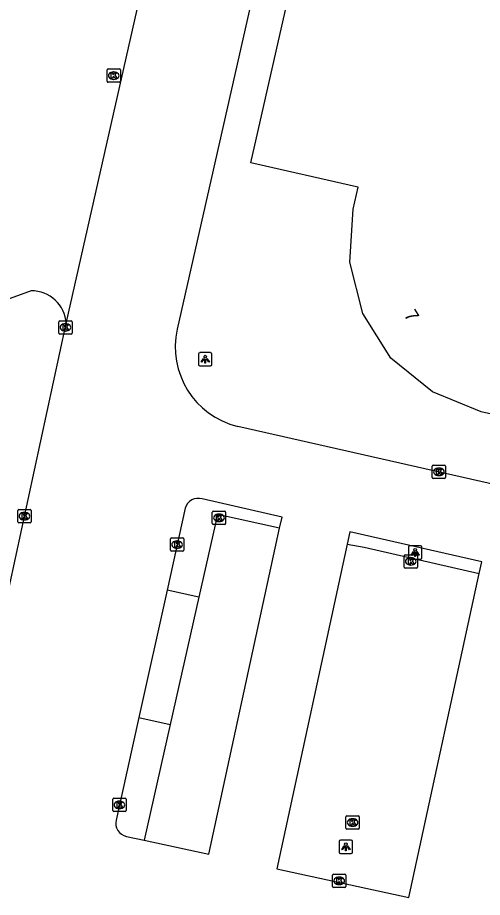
# Model space of a CAD drawing. Extents: x 162172 to 163187, y 382874 to 383684.
# Drawn here: x 162441.7 to 162476.6, y 383058.6 to 383124.7 of the extents above; entities that cross this region are included whole.
import ezdxf

# ---------------------------------------------------------------- set-up
doc = ezdxf.new("R2010")
doc.units = 0
for name, color, linetype in [('IMGEO_Kolk', 7, 'Continuous'), ('IMGEO_Lichtpunt', 7, 'Continuous'), ('IMGEO_Pand', 7, 'Continuous'), ('IMGEO_Pand_nummerreeks', 7, 'Continuous'), ('IMGEO_Parkeervlak_open', 7, 'Continuous'), ('IMGEO_Rijbaan_lokaal_open', 7, 'Continuous'), ('IMGEO_Verkeerseiland_open', 7, 'Continuous')]:
    doc.layers.add(name, color=color, linetype=linetype)

msp = doc.modelspace()

# ---------------------------------------------------------------- linework, layer by layer
at = {"layer": 'IMGEO_Kolk'}
for p, q in [((162448.37, 383119.928), (162448.37, 383120.78)), ((162448.445, 383120.854), (162449.297, 383120.854)), ((162448.858, 383120.634), (162448.883, 383120.634)), ((162449.371, 383120.78), (162449.371, 383119.928)), ((162448.881, 383120.074), (162448.856, 383120.074)), ((162449.297, 383119.854), (162448.445, 383119.854)), ((162444.742, 383101.004), (162444.742, 383101.856)), ((162444.817, 383101.93), (162445.669, 383101.93)), ((162445.23, 383101.71), (162445.255, 383101.71)), ((162445.743, 383101.856), (162445.743, 383101.004)), ((162445.669, 383100.93), (162444.817, 383100.93)), ((162445.253, 383101.15), (162445.228, 383101.15)), ((162472.796, 383090.145), (162472.796, 383090.997)), ((162472.871, 383091.071), (162473.723, 383091.071)), ((162473.284, 383090.851), (162473.309, 383090.851)), ((162473.797, 383090.997), (162473.797, 383090.145)), ((162473.307, 383090.291), (162473.282, 383090.291)), ((162473.723, 383090.071), (162472.871, 383090.071)), ((162441.663, 383086.813), (162441.663, 383087.665)), ((162441.738, 383087.739), (162442.59, 383087.739)), ((162442.151, 383087.519), (162442.176, 383087.519)), ((162442.664, 383087.665), (162442.664, 383086.813)), ((162456.278, 383086.688), (162456.278, 383087.54)), ((162456.353, 383087.614), (162457.205, 383087.614)), ((162457.279, 383087.54), (162457.279, 383086.688)), ((162442.174, 383086.959), (162442.149, 383086.959)), ((162456.766, 383087.394), (162456.791, 383087.394)), ((162442.59, 383086.739), (162441.738, 383086.739)), ((162457.205, 383086.614), (162456.353, 383086.614)), ((162456.789, 383086.834), (162456.764, 383086.834)), ((162453.209, 383085.599), (162454.061, 383085.599)), ((162453.134, 383084.673), (162453.134, 383085.525)), ((162453.622, 383085.379), (162453.647, 383085.379)), ((162454.135, 383085.525), (162454.135, 383084.673)), ((162454.061, 383084.599), (162453.209, 383084.599)), ((162453.645, 383084.819), (162453.62, 383084.819)), ((162470.685, 383083.413), (162470.685, 383084.265)), ((162470.76, 383084.339), (162471.612, 383084.339)), ((162471.686, 383084.265), (162471.686, 383083.413)), ((162471.196, 383083.559), (162471.171, 383083.559)), ((162471.173, 383084.119), (162471.198, 383084.119)), ((162471.612, 383083.339), (162470.76, 383083.339)), ((162448.798, 383065.105), (162448.798, 383065.957)), ((162448.873, 383066.031), (162449.725, 383066.031)), ((162449.286, 383065.811), (162449.311, 383065.811)), ((162449.799, 383065.957), (162449.799, 383065.105)), ((162449.725, 383065.031), (162448.873, 383065.031)), ((162449.309, 383065.251), (162449.284, 383065.251)), ((162466.317, 383063.782), (162466.317, 383064.634)), ((162466.392, 383064.708), (162467.244, 383064.708)), ((162466.805, 383064.488), (162466.83, 383064.488)), ((162467.318, 383064.634), (162467.318, 383063.782)), ((162467.244, 383063.708), (162466.392, 383063.708)), ((162466.828, 383063.928), (162466.803, 383063.928)), ((162465.307, 383059.396), (162465.307, 383060.248)), ((162465.382, 383060.322), (162466.234, 383060.322)), ((162465.795, 383060.102), (162465.82, 383060.102)), ((162466.308, 383060.248), (162466.308, 383059.396)), ((162466.234, 383059.322), (162465.382, 383059.322)), ((162465.818, 383059.542), (162465.793, 383059.542))]:
    msp.add_line(p, q, dxfattribs=at)
for points in [[(162448.37, 383119.928), (162448.37, 383120.78)], [(162448.445, 383120.854), (162449.297, 383120.854)], [(162449.371, 383120.78), (162449.371, 383119.928)], [(162448.691, 383120.554), (162448.814, 383120.554), (162448.814, 383120.403), (162448.944, 383120.554), (162449.108, 383120.554), (162448.962, 383120.403), (162449.115, 383120.154), (162448.963, 383120.154), (162448.878, 383120.318), (162448.814, 383120.251), (162448.814, 383120.154), (162448.691, 383120.154), (162448.691, 383120.554)], [(162449.297, 383119.854), (162448.445, 383119.854)], [(162444.742, 383101.004), (162444.742, 383101.856)], [(162444.817, 383101.93), (162445.669, 383101.93)], [(162445.063, 383101.63), (162445.186, 383101.63), (162445.186, 383101.479), (162445.316, 383101.63), (162445.48, 383101.63), (162445.334, 383101.479), (162445.487, 383101.23), (162445.335, 383101.23), (162445.25, 383101.394), (162445.186, 383101.327), (162445.186, 383101.23), (162445.063, 383101.23), (162445.063, 383101.63)], [(162445.743, 383101.856), (162445.743, 383101.004)], [(162445.669, 383100.93), (162444.817, 383100.93)], [(162472.796, 383090.145), (162472.796, 383090.997)], [(162472.871, 383091.071), (162473.723, 383091.071)], [(162473.797, 383090.997), (162473.797, 383090.145)], [(162473.117, 383090.771), (162473.24, 383090.771), (162473.24, 383090.62), (162473.37, 383090.771), (162473.534, 383090.771), (162473.388, 383090.62), (162473.541, 383090.371), (162473.389, 383090.371), (162473.304, 383090.535), (162473.24, 383090.468), (162473.24, 383090.371), (162473.117, 383090.371), (162473.117, 383090.771)], [(162473.723, 383090.071), (162472.871, 383090.071)], [(162441.663, 383086.813), (162441.663, 383087.665)], [(162441.738, 383087.739), (162442.59, 383087.739)], [(162442.664, 383087.665), (162442.664, 383086.813)], [(162456.278, 383086.688), (162456.278, 383087.54)], [(162456.353, 383087.614), (162457.205, 383087.614)], [(162457.279, 383087.54), (162457.279, 383086.688)], [(162441.984, 383087.439), (162442.107, 383087.439), (162442.107, 383087.288), (162442.237, 383087.439), (162442.401, 383087.439), (162442.255, 383087.288), (162442.408, 383087.039), (162442.256, 383087.039), (162442.171, 383087.203), (162442.107, 383087.136), (162442.107, 383087.039), (162441.984, 383087.039), (162441.984, 383087.439)], [(162456.599, 383087.314), (162456.722, 383087.314), (162456.722, 383087.163), (162456.852, 383087.314), (162457.016, 383087.314), (162456.87, 383087.163), (162457.023, 383086.914), (162456.871, 383086.914), (162456.786, 383087.078), (162456.722, 383087.011), (162456.722, 383086.914), (162456.599, 383086.914), (162456.599, 383087.314)], [(162442.59, 383086.739), (162441.738, 383086.739)], [(162457.205, 383086.614), (162456.353, 383086.614)], [(162453.209, 383085.599), (162454.061, 383085.599)], [(162453.134, 383084.673), (162453.134, 383085.525)], [(162453.455, 383085.299), (162453.578, 383085.299), (162453.578, 383085.148), (162453.708, 383085.299), (162453.872, 383085.299), (162453.726, 383085.148), (162453.879, 383084.899), (162453.727, 383084.899), (162453.642, 383085.063), (162453.578, 383084.996), (162453.578, 383084.899), (162453.455, 383084.899), (162453.455, 383085.299)], [(162454.135, 383085.525), (162454.135, 383084.673)], [(162454.061, 383084.599), (162453.209, 383084.599)], [(162470.685, 383083.413), (162470.685, 383084.265)], [(162470.76, 383084.339), (162471.612, 383084.339)], [(162471.686, 383084.265), (162471.686, 383083.413)], [(162471.006, 383084.039), (162471.129, 383084.039), (162471.129, 383083.888), (162471.259, 383084.039), (162471.423, 383084.039), (162471.277, 383083.888), (162471.43, 383083.639), (162471.278, 383083.639), (162471.193, 383083.803), (162471.129, 383083.736), (162471.129, 383083.639), (162471.006, 383083.639), (162471.006, 383084.039)], [(162471.612, 383083.339), (162470.76, 383083.339)], [(162448.798, 383065.105), (162448.798, 383065.957)], [(162448.873, 383066.031), (162449.725, 383066.031)], [(162449.119, 383065.731), (162449.242, 383065.731), (162449.242, 383065.58), (162449.372, 383065.731), (162449.536, 383065.731), (162449.39, 383065.58), (162449.543, 383065.331), (162449.391, 383065.331), (162449.306, 383065.495), (162449.242, 383065.428), (162449.242, 383065.331), (162449.119, 383065.331), (162449.119, 383065.731)], [(162449.799, 383065.957), (162449.799, 383065.105)], [(162449.725, 383065.031), (162448.873, 383065.031)], [(162466.317, 383063.782), (162466.317, 383064.634)], [(162466.392, 383064.708), (162467.244, 383064.708)], [(162466.638, 383064.408), (162466.761, 383064.408), (162466.761, 383064.257), (162466.891, 383064.408), (162467.055, 383064.408), (162466.909, 383064.257), (162467.062, 383064.008), (162466.91, 383064.008), (162466.825, 383064.172), (162466.761, 383064.105), (162466.761, 383064.008), (162466.638, 383064.008), (162466.638, 383064.408)], [(162467.318, 383064.634), (162467.318, 383063.782)], [(162467.244, 383063.708), (162466.392, 383063.708)], [(162465.307, 383059.396), (162465.307, 383060.248)], [(162465.382, 383060.322), (162466.234, 383060.322)], [(162465.628, 383060.022), (162465.751, 383060.022), (162465.751, 383059.871), (162465.881, 383060.022), (162466.045, 383060.022), (162465.899, 383059.871), (162466.052, 383059.622), (162465.9, 383059.622), (162465.815, 383059.786), (162465.751, 383059.719), (162465.751, 383059.622), (162465.628, 383059.622), (162465.628, 383060.022)], [(162466.308, 383060.248), (162466.308, 383059.396)], [(162466.234, 383059.322), (162465.382, 383059.322)]]:
    msp.add_lwpolyline(points, dxfattribs=at)
for centre, start, end in [((162448.447, 383120.778), 91.55205, 178.44795), ((162448.447, 383120.778), 91.55205, 178.44795), ((162449.295, 383120.778), 1.55205, 88.44795), ((162449.295, 383120.778), 1.55205, 88.44795), ((162448.447, 383119.93), 181.55205, 268.44795), ((162448.447, 383119.93), 181.55205, 268.44795), ((162449.295, 383119.93), 271.55205, 358.44795), ((162449.295, 383119.93), 271.55205, 358.44795), ((162444.819, 383101.854), 91.55205, 178.44795), ((162444.819, 383101.854), 91.55205, 178.44795), ((162445.667, 383101.854), 1.55205, 88.44795), ((162445.667, 383101.854), 1.55205, 88.44795), ((162444.819, 383101.006), 181.55205, 268.44795), ((162444.819, 383101.006), 181.55205, 268.44795), ((162445.667, 383101.006), 271.55205, 358.44795), ((162445.667, 383101.006), 271.55205, 358.44795), ((162472.873, 383090.995), 91.55205, 178.44795), ((162472.873, 383090.995), 91.55205, 178.44795), ((162473.721, 383090.995), 1.55205, 88.44795), ((162473.721, 383090.995), 1.55205, 88.44795), ((162472.873, 383090.147), 181.55205, 268.44795), ((162472.873, 383090.147), 181.55205, 268.44795), ((162473.721, 383090.147), 271.55205, 358.44795), ((162473.721, 383090.147), 271.55205, 358.44795), ((162441.74, 383087.663), 91.55205, 178.44795), ((162441.74, 383087.663), 91.55205, 178.44795), ((162442.588, 383087.663), 1.55205, 88.44795), ((162442.588, 383087.663), 1.55205, 88.44795), ((162456.355, 383087.538), 91.55205, 178.44795), ((162456.355, 383087.538), 91.55205, 178.44795), ((162457.203, 383087.538), 1.55205, 88.44795), ((162457.203, 383087.538), 1.55205, 88.44795), ((162441.74, 383086.815), 181.55205, 268.44795), ((162441.74, 383086.815), 181.55205, 268.44795), ((162442.588, 383086.815), 271.55205, 358.44795), ((162442.588, 383086.815), 271.55205, 358.44795), ((162456.355, 383086.69), 181.55205, 268.44795), ((162456.355, 383086.69), 181.55205, 268.44795), ((162457.203, 383086.69), 271.55205, 358.44795), ((162457.203, 383086.69), 271.55205, 358.44795), ((162453.211, 383085.523), 91.55205, 178.44795), ((162453.211, 383085.523), 91.55205, 178.44795), ((162454.059, 383085.523), 1.55205, 88.44795), ((162454.059, 383085.523), 1.55205, 88.44795), ((162453.211, 383084.675), 181.55205, 268.44795), ((162453.211, 383084.675), 181.55205, 268.44795), ((162454.059, 383084.675), 271.55205, 358.44795), ((162454.059, 383084.675), 271.55205, 358.44795), ((162470.762, 383084.263), 91.55205, 178.44795), ((162470.762, 383084.263), 91.55205, 178.44795), ((162471.61, 383084.263), 1.55205, 88.44795), ((162471.61, 383084.263), 1.55205, 88.44795), ((162470.762, 383083.415), 181.55205, 268.44795), ((162470.762, 383083.415), 181.55205, 268.44795), ((162471.61, 383083.415), 271.55205, 358.44795), ((162471.61, 383083.415), 271.55205, 358.44795), ((162448.875, 383065.955), 91.55205, 178.44795), ((162448.875, 383065.955), 91.55205, 178.44795), ((162449.723, 383065.955), 1.55205, 88.44795), ((162449.723, 383065.955), 1.55205, 88.44795), ((162448.875, 383065.107), 181.55205, 268.44795), ((162448.875, 383065.107), 181.55205, 268.44795), ((162449.723, 383065.107), 271.55205, 358.44795), ((162449.723, 383065.107), 271.55205, 358.44795), ((162466.394, 383064.632), 91.55205, 178.44795), ((162466.394, 383064.632), 91.55205, 178.44795), ((162467.242, 383064.632), 1.55205, 88.44795), ((162467.242, 383064.632), 1.55205, 88.44795), ((162466.394, 383063.784), 181.55205, 268.44795), ((162466.394, 383063.784), 181.55205, 268.44795), ((162467.242, 383063.784), 271.55205, 358.44795), ((162467.242, 383063.784), 271.55205, 358.44795), ((162465.384, 383060.246), 91.55205, 178.44795), ((162465.384, 383060.246), 91.55205, 178.44795), ((162466.232, 383060.246), 1.55205, 88.44795), ((162466.232, 383060.246), 1.55205, 88.44795), ((162465.384, 383059.398), 181.55205, 268.44795), ((162465.384, 383059.398), 181.55205, 268.44795), ((162466.232, 383059.398), 271.55205, 358.44795), ((162466.232, 383059.398), 271.55205, 358.44795)]:
    msp.add_arc(centre, 0.0765, start, end, dxfattribs=at)
for centre, major_axis, ratio, start_param, end_param in [((162448.857, 383120.354), (-0.387, 0.002), 0.722429, 4.712389, 7.853982), ((162448.882, 383120.354), (-0.39, 0.002), 0.717154, 1.570796, 4.712389), ((162445.229, 383101.43), (-0.387, 0.002), 0.722429, 4.712389, 7.853982), ((162445.254, 383101.43), (-0.39, 0.002), 0.717154, 1.570796, 4.712389), ((162473.283, 383090.571), (-0.387, 0.002), 0.722429, 4.712389, 7.853982), ((162473.308, 383090.571), (-0.39, 0.002), 0.717154, 1.570796, 4.712389), ((162442.15, 383087.239), (-0.387, 0.002), 0.722429, 4.712389, 7.853982), ((162442.175, 383087.239), (-0.39, 0.002), 0.717154, 1.570796, 4.712389), ((162456.765, 383087.114), (-0.387, 0.002), 0.722429, 4.712389, 7.853982), ((162456.79, 383087.114), (-0.39, 0.002), 0.717154, 1.570796, 4.712389), ((162453.621, 383085.099), (-0.387, 0.002), 0.722429, 4.712389, 7.853982), ((162453.646, 383085.099), (-0.39, 0.002), 0.717154, 1.570796, 4.712389), ((162471.172, 383083.839), (-0.387, 0.002), 0.722429, 4.712389, 7.853982), ((162471.197, 383083.839), (-0.39, 0.002), 0.717154, 1.570796, 4.712389), ((162449.285, 383065.531), (-0.387, 0.002), 0.722429, 4.712389, 7.853982), ((162449.31, 383065.531), (-0.39, 0.002), 0.717154, 1.570796, 4.712389), ((162466.804, 383064.208), (-0.387, 0.002), 0.722429, 4.712389, 7.853982), ((162466.829, 383064.208), (-0.39, 0.002), 0.717154, 1.570796, 4.712389), ((162465.794, 383059.822), (-0.387, 0.002), 0.722429, 4.712389, 7.853982), ((162465.819, 383059.822), (-0.39, 0.002), 0.717154, 1.570796, 4.712389)]:
    msp.add_ellipse(centre, major_axis=major_axis, ratio=ratio, start_param=start_param, end_param=end_param, dxfattribs=at)
at = {"layer": 'IMGEO_Lichtpunt'}
for p, q in [((162455.249, 383099.434), (162455.249, 383098.627)), ((162455.249, 383099.434), (162455.249, 383098.627)), ((162456.151, 383099.529), (162455.343, 383099.529)), ((162456.151, 383099.529), (162455.343, 383099.529)), ((162456.245, 383098.627), (162456.245, 383099.434)), ((162456.245, 383098.627), (162456.245, 383099.434)), ((162455.343, 383098.533), (162456.151, 383098.533)), ((162455.343, 383098.533), (162456.151, 383098.533)), ((162471.014, 383084.906), (162471.014, 383084.099)), ((162471.014, 383084.906), (162471.014, 383084.099)), ((162471.916, 383085.001), (162471.108, 383085.001)), ((162471.916, 383085.001), (162471.108, 383085.001)), ((162472.01, 383084.099), (162472.01, 383084.906)), ((162472.01, 383084.099), (162472.01, 383084.906)), ((162471.108, 383084.005), (162471.916, 383084.005)), ((162471.108, 383084.005), (162471.916, 383084.005)), ((162465.813, 383062.788), (162465.813, 383061.981)), ((162465.813, 383062.788), (162465.813, 383061.981)), ((162466.715, 383062.883), (162465.907, 383062.883)), ((162466.715, 383062.883), (162465.907, 383062.883)), ((162466.809, 383061.981), (162466.809, 383062.788)), ((162466.809, 383061.981), (162466.809, 383062.788)), ((162465.907, 383061.887), (162466.715, 383061.887)), ((162465.907, 383061.887), (162466.715, 383061.887))]:
    msp.add_line(p, q, dxfattribs=at)
for points in [[(162455.623, 383099.098), (162455.662, 383099.07), (162455.474, 383098.808), (162455.436, 383098.835), (162455.623, 383099.098)], [(162455.725, 383099.05), (162455.772, 383099.05), (162455.772, 383098.728), (162455.725, 383098.728), (162455.725, 383099.05)], [(162455.835, 383099.07), (162455.873, 383099.097), (162456.06, 383098.835), (162456.021, 383098.807), (162455.835, 383099.07)], [(162471.388, 383084.57), (162471.427, 383084.542), (162471.239, 383084.28), (162471.201, 383084.307), (162471.388, 383084.57)], [(162471.49, 383084.522), (162471.537, 383084.522), (162471.537, 383084.2), (162471.49, 383084.2), (162471.49, 383084.522)], [(162471.6, 383084.542), (162471.638, 383084.569), (162471.825, 383084.307), (162471.786, 383084.279), (162471.6, 383084.542)], [(162466.187, 383062.452), (162466.226, 383062.424), (162466.038, 383062.162), (162466, 383062.189), (162466.187, 383062.452)], [(162466.289, 383062.404), (162466.336, 383062.404), (162466.336, 383062.082), (162466.289, 383062.082), (162466.289, 383062.404)], [(162466.399, 383062.424), (162466.437, 383062.451), (162466.624, 383062.189), (162466.585, 383062.161), (162466.399, 383062.424)]]:
    msp.add_lwpolyline(points, dxfattribs=at)
for centre in [(162455.748, 383099.232), (162471.513, 383084.704), (162466.312, 383062.586)]:
    msp.add_circle(centre, 0.0994, dxfattribs=at)
for centre, start, end in [((162455.343, 383099.434), 90, 180), ((162455.343, 383099.434), 90, 180), ((162456.151, 383099.434), 0, 90), ((162456.151, 383099.434), 0, 90), ((162455.343, 383098.627), 180, 270), ((162455.343, 383098.627), 180, 270), ((162456.151, 383098.627), 270, 0), ((162456.151, 383098.627), 270, 360), ((162471.108, 383084.906), 90, 180), ((162471.108, 383084.906), 90, 180), ((162471.916, 383084.906), 0, 90), ((162471.916, 383084.906), 0, 90), ((162471.108, 383084.099), 180, 270), ((162471.108, 383084.099), 180, 270), ((162471.916, 383084.099), 270, 0), ((162471.916, 383084.099), 270, 360), ((162465.907, 383062.788), 90, 180), ((162465.907, 383062.788), 90, 180), ((162466.715, 383062.788), 0, 90), ((162466.715, 383062.788), 0, 90), ((162465.907, 383061.981), 180, 270), ((162465.907, 383061.981), 180, 270), ((162466.715, 383061.981), 270, 0), ((162466.715, 383061.981), 270, 360)]:
    msp.add_arc(centre, 0.0946, start, end, dxfattribs=at)
at = {"layer": 'IMGEO_Pand'}
msp.add_lwpolyline([(162484.409, 383093.295), (162476.459, 383095.089), (162472.808, 383096.577), (162469.691, 383099.116), (162467.591, 383102.472), (162466.614, 383106.341), (162466.852, 383110.317), (162467.227, 383111.979), (162467.097, 383112.008), (162459.164, 383113.794), (162460.267, 383118.672), (162473.143, 383175.448), (162481.648, 383173.568)], dxfattribs=at)
at = {"layer": 'IMGEO_Parkeervlak_open'}
for points in [[(162461.32, 383086.325), (162456.658, 383087.352), (162455.266, 383081.151)], [(162466.411, 383085.133), (162467.671, 383084.906), (162476.314, 383082.933)], [(162455.266, 383081.151), (162453.117, 383071.583)], [(162453.117, 383071.583), (162451.164, 383062.883)]]:
    msp.add_lwpolyline(points, dxfattribs=at)
at = {"layer": 'IMGEO_Rijbaan_lokaal_open'}
for points in [[(162464.935, 383151.236), (162453.647, 383101.297)], [(162445.304, 383101.713), (162452.054, 383131.655)], [(162442.66, 383104.175), (162435.169, 383101.446)], [(162438.868, 383070.439), (162438.579, 383070.494), (162439.089, 383073.065), (162445.304, 383101.713)], [(162458.188, 383093.991), (162541.036, 383075.236)], [(162461.32, 383086.325), (162461.535, 383087.161), (162455.508, 383088.54)], [(162454.242, 383087.836), (162452.878, 383081.68)], [(162451.164, 383062.883), (162456.015, 383061.832), (162461.32, 383086.325)], [(162476.314, 383082.933), (162476.508, 383083.796), (162466.596, 383086.052), (162466.411, 383085.133)], [(162466.411, 383085.133), (162461.124, 383060.726), (162471.038, 383058.578), (162476.314, 383082.933)], [(162452.878, 383081.68), (162450.758, 383072.113)], [(162450.758, 383072.113), (162449.047, 383064.393)], [(162449.826, 383063.167), (162451.164, 383062.883)]]:
    msp.add_lwpolyline(points, dxfattribs=at)
for centre, radius, start, end in [((162442.713, 383101.582), 2.594, 2.90546, 91.17735), ((162459.62, 383099.945), 6.124, 167.24741, 256.47812), ((162455.22, 383087.568), 1.014, 73.48593, 164.66938), ((162450.038, 383064.162), 1.018, 166.90495, 257.95878)]:
    msp.add_arc(centre, radius, start, end, dxfattribs=at)
at = {"layer": 'IMGEO_Verkeerseiland_open'}
for points in [[(162455.266, 383081.151), (162452.878, 383081.68)], [(162450.758, 383072.113), (162453.117, 383071.583)]]:
    msp.add_lwpolyline(points, dxfattribs=at)

# ---------------------------------------------------------------- texts
at = {"layer": 'IMGEO_Pand_nummerreeks'}
msp.add_text('7', height=1, rotation=302.03386, dxfattribs=at).set_placement((162470.631, 383102.363))

doc.saveas('drawing.dxf')
